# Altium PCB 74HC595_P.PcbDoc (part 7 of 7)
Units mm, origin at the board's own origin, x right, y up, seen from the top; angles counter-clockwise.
Board outline 89.11 x 89.03 mm, 2 copper layers (Top Layer, Bottom Layer); 552 components, 23 nets, 1488 pads, 408 vias.
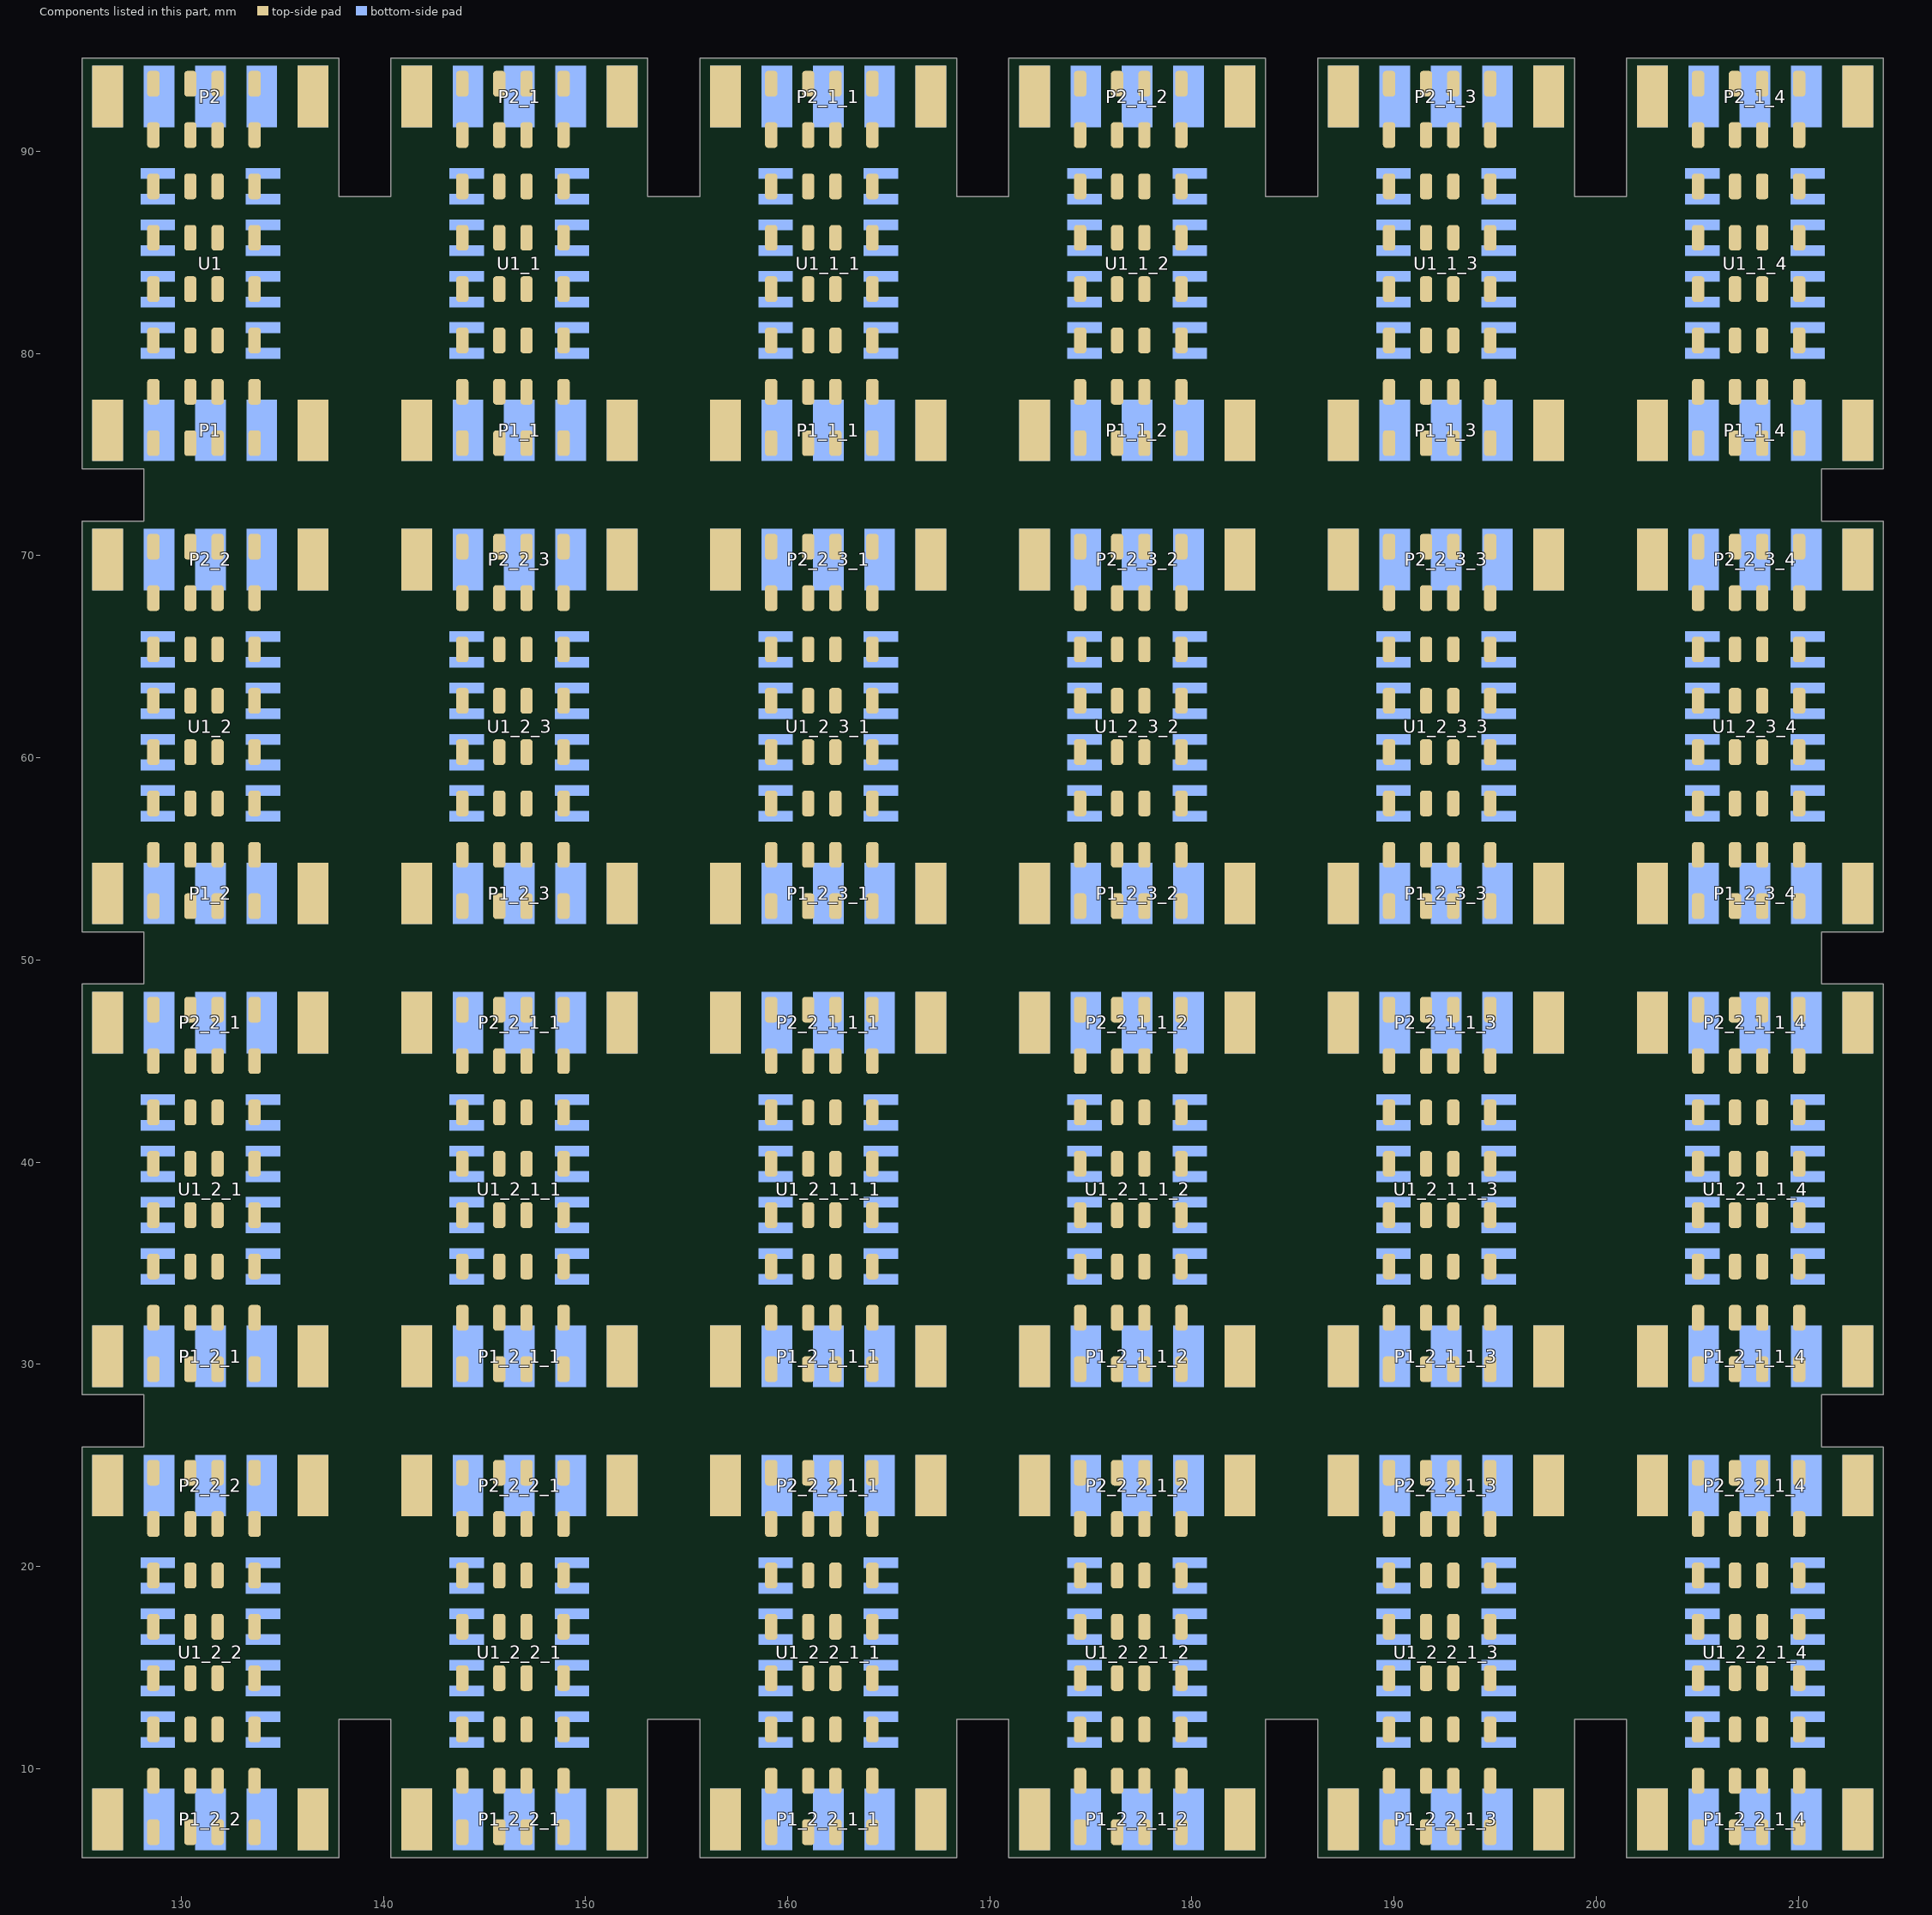
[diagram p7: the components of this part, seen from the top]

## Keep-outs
Keep-Out Layer:
  circle w0.1: c205.95,26.036 r0.275
  circle w0.1: c205.188,26.036 r0.275
  circle w0.1: c206.712,26.036 r0.275
  circle w0.1: c207.474,26.036 r0.275
  circle w0.1: c208.236,26.036 r0.275
  circle w0.1: c208.998,26.036 r0.275
  circle w0.1: c209.76,26.036 r0.275
  circle w0.1: c210.522,26.036 r0.275
  circle w0.1: c210.522,28.364 r0.275
  circle w0.1: c209.76,28.364 r0.275
  circle w0.1: c208.998,28.364 r0.275
  circle w0.1: c208.236,28.364 r0.275
  circle w0.1: c207.474,28.364 r0.275
  circle w0.1: c206.712,28.364 r0.275
  circle w0.1: c205.188,28.364 r0.275
  circle w0.1: c205.95,28.364 r0.275
  circle w0.1: c190.668,26.036 r0.275
  circle w0.1: c189.906,26.036 r0.275
  circle w0.1: c191.43,26.036 r0.275
  circle w0.1: c192.192,26.036 r0.275
  circle w0.1: c192.954,26.036 r0.275
  circle w0.1: c193.716,26.036 r0.275
  circle w0.1: c194.478,26.036 r0.275
  circle w0.1: c195.24,26.036 r0.275
  circle w0.1: c195.24,28.364 r0.275
  circle w0.1: c194.478,28.364 r0.275
  circle w0.1: c193.716,28.364 r0.275
  circle w0.1: c192.954,28.364 r0.275
  circle w0.1: c192.192,28.364 r0.275
  circle w0.1: c191.43,28.364 r0.275
  circle w0.1: c189.906,28.364 r0.275
  circle w0.1: c190.668,28.364 r0.275
  circle w0.1: c175.386,26.036 r0.275
  circle w0.1: c174.624,26.036 r0.275
  circle w0.1: c176.148,26.036 r0.275
  circle w0.1: c176.91,26.036 r0.275
  circle w0.1: c177.672,26.036 r0.275
  circle w0.1: c178.434,26.036 r0.275
  circle w0.1: c179.196,26.036 r0.275
  circle w0.1: c179.958,26.036 r0.275
  circle w0.1: c179.958,28.364 r0.275
  circle w0.1: c179.196,28.364 r0.275
  circle w0.1: c178.434,28.364 r0.275
  circle w0.1: c177.672,28.364 r0.275
  circle w0.1: c176.91,28.364 r0.275
  circle w0.1: c176.148,28.364 r0.275
  circle w0.1: c174.624,28.364 r0.275
  circle w0.1: c175.386,28.364 r0.275
  circle w0.1: c160.104,26.036 r0.275
  circle w0.1: c159.342,26.036 r0.275
  circle w0.1: c160.866,26.036 r0.275
  circle w0.1: c161.628,26.036 r0.275
  circle w0.1: c162.39,26.036 r0.275
  circle w0.1: c163.152,26.036 r0.275
  circle w0.1: c163.914,26.036 r0.275
  circle w0.1: c164.676,26.036 r0.275
  circle w0.1: c164.676,28.364 r0.275
  circle w0.1: c163.914,28.364 r0.275
  circle w0.1: c163.152,28.364 r0.275
  circle w0.1: c162.39,28.364 r0.275
  circle w0.1: c161.628,28.364 r0.275
  circle w0.1: c160.866,28.364 r0.275
  circle w0.1: c159.342,28.364 r0.275
  circle w0.1: c160.104,28.364 r0.275
  circle w0.1: c144.822,26.036 r0.275
  circle w0.1: c144.06,26.036 r0.275
  circle w0.1: c145.584,26.036 r0.275
  circle w0.1: c146.346,26.036 r0.275
  circle w0.1: c147.108,26.036 r0.275
  circle w0.1: c147.87,26.036 r0.275
  circle w0.1: c148.632,26.036 r0.275
  circle w0.1: c149.394,26.036 r0.275
  circle w0.1: c149.394,28.364 r0.275
  circle w0.1: c148.632,28.364 r0.275
  circle w0.1: c147.87,28.364 r0.275
  circle w0.1: c147.108,28.364 r0.275
  circle w0.1: c146.346,28.364 r0.275
  circle w0.1: c145.584,28.364 r0.275
  circle w0.1: c144.06,28.364 r0.275
  circle w0.1: c144.822,28.364 r0.275
  circle w0.1: c129.54,26.036 r0.275
  circle w0.1: c128.778,26.036 r0.275
  circle w0.1: c130.302,26.036 r0.275
  circle w0.1: c131.064,26.036 r0.275
  circle w0.1: c131.826,26.036 r0.275
  circle w0.1: c132.588,26.036 r0.275
  circle w0.1: c133.35,26.036 r0.275
  circle w0.1: c134.112,26.036 r0.275
  circle w0.1: c134.112,28.364 r0.275
  circle w0.1: c133.35,28.364 r0.275
  circle w0.1: c132.588,28.364 r0.275
  circle w0.1: c131.826,28.364 r0.275
  circle w0.1: c131.064,28.364 r0.275
  circle w0.1: c130.302,28.364 r0.275
  circle w0.1: c128.778,28.364 r0.275
  circle w0.1: c129.54,28.364 r0.275
  circle w0.1: c205.95,48.938 r0.275
  circle w0.1: c205.188,48.938 r0.275
  circle w0.1: c206.712,48.938 r0.275
  circle w0.1: c207.474,48.938 r0.275
  circle w0.1: c208.236,48.938 r0.275
  circle w0.1: c208.998,48.938 r0.275
  circle w0.1: c209.76,48.938 r0.275
  circle w0.1: c210.522,48.938 r0.275
  circle w0.1: c210.522,51.266 r0.275
  circle w0.1: c209.76,51.266 r0.275
  circle w0.1: c208.998,51.266 r0.275
  circle w0.1: c208.236,51.266 r0.275
  circle w0.1: c207.474,51.266 r0.275
  circle w0.1: c206.712,51.266 r0.275
  circle w0.1: c205.188,51.266 r0.275
  circle w0.1: c205.95,51.266 r0.275
  circle w0.1: c190.668,48.938 r0.275
  circle w0.1: c189.906,48.938 r0.275
  circle w0.1: c191.43,48.938 r0.275
  circle w0.1: c192.192,48.938 r0.275
  circle w0.1: c192.954,48.938 r0.275
  circle w0.1: c193.716,48.938 r0.275
  circle w0.1: c194.478,48.938 r0.275
  circle w0.1: c195.24,48.938 r0.275
  circle w0.1: c195.24,51.266 r0.275
  circle w0.1: c194.478,51.266 r0.275
  circle w0.1: c193.716,51.266 r0.275
  circle w0.1: c192.954,51.266 r0.275
  circle w0.1: c192.192,51.266 r0.275
  circle w0.1: c191.43,51.266 r0.275
  circle w0.1: c189.906,51.266 r0.275
  circle w0.1: c190.668,51.266 r0.275
  circle w0.1: c175.386,48.938 r0.275
  circle w0.1: c174.624,48.938 r0.275
  circle w0.1: c176.148,48.938 r0.275
  circle w0.1: c176.91,48.938 r0.275
  circle w0.1: c177.672,48.938 r0.275
  circle w0.1: c178.434,48.938 r0.275
  circle w0.1: c179.196,48.938 r0.275
  circle w0.1: c179.958,48.938 r0.275
  circle w0.1: c179.958,51.266 r0.275
  circle w0.1: c179.196,51.266 r0.275
  circle w0.1: c178.434,51.266 r0.275
  circle w0.1: c177.672,51.266 r0.275
  circle w0.1: c176.91,51.266 r0.275
  circle w0.1: c176.148,51.266 r0.275
  circle w0.1: c174.624,51.266 r0.275
  circle w0.1: c175.386,51.266 r0.275
  circle w0.1: c160.104,48.938 r0.275
  circle w0.1: c159.342,48.938 r0.275
  circle w0.1: c160.866,48.938 r0.275
  circle w0.1: c161.628,48.938 r0.275
  circle w0.1: c162.39,48.938 r0.275
  circle w0.1: c163.152,48.938 r0.275
  circle w0.1: c163.914,48.938 r0.275
  circle w0.1: c164.676,48.938 r0.275
  circle w0.1: c164.676,51.266 r0.275
  circle w0.1: c163.914,51.266 r0.275
  circle w0.1: c163.152,51.266 r0.275
  circle w0.1: c162.39,51.266 r0.275
  circle w0.1: c161.628,51.266 r0.275
  circle w0.1: c160.866,51.266 r0.275
  circle w0.1: c159.342,51.266 r0.275
  circle w0.1: c160.104,51.266 r0.275
  circle w0.1: c144.822,48.938 r0.275
  circle w0.1: c144.06,48.938 r0.275
  circle w0.1: c145.584,48.938 r0.275
  circle w0.1: c146.346,48.938 r0.275
  circle w0.1: c147.108,48.938 r0.275
  circle w0.1: c147.87,48.938 r0.275
  circle w0.1: c148.632,48.938 r0.275
  circle w0.1: c149.394,48.938 r0.275
  circle w0.1: c149.394,51.266 r0.275
  circle w0.1: c148.632,51.266 r0.275
  circle w0.1: c147.87,51.266 r0.275
  circle w0.1: c147.108,51.266 r0.275
  circle w0.1: c146.346,51.266 r0.275
  circle w0.1: c145.584,51.266 r0.275
  circle w0.1: c144.06,51.266 r0.275
  circle w0.1: c144.822,51.266 r0.275
  circle w0.1: c129.54,48.938 r0.275
  circle w0.1: c128.778,48.938 r0.275
  circle w0.1: c130.302,48.938 r0.275
  circle w0.1: c131.064,48.938 r0.275
  circle w0.1: c131.826,48.938 r0.275
  circle w0.1: c132.588,48.938 r0.275
  circle w0.1: c133.35,48.938 r0.275
  circle w0.1: c134.112,48.938 r0.275
  circle w0.1: c134.112,51.266 r0.275
  circle w0.1: c133.35,51.266 r0.275
  circle w0.1: c132.588,51.266 r0.275
  circle w0.1: c131.826,51.266 r0.275
  circle w0.1: c131.064,51.266 r0.275
  circle w0.1: c130.302,51.266 r0.275
  circle w0.1: c128.778,51.266 r0.275
  circle w0.1: c129.54,51.266 r0.275
  circle w0.1: c205.95,71.84 r0.275
  circle w0.1: c205.188,71.84 r0.275
  circle w0.1: c206.712,71.84 r0.275
  circle w0.1: c207.474,71.84 r0.275
  circle w0.1: c208.236,71.84 r0.275
  circle w0.1: c208.998,71.84 r0.275
  circle w0.1: c209.76,71.84 r0.275
  circle w0.1: c210.522,71.84 r0.275
  circle w0.1: c210.522,74.168 r0.275
  circle w0.1: c209.76,74.168 r0.275
  circle w0.1: c208.998,74.168 r0.275
  circle w0.1: c208.236,74.168 r0.275
  circle w0.1: c207.474,74.168 r0.275
  circle w0.1: c206.712,74.168 r0.275
  circle w0.1: c205.188,74.168 r0.275
  circle w0.1: c205.95,74.168 r0.275
  circle w0.1: c190.668,71.84 r0.275
  circle w0.1: c189.906,71.84 r0.275
  circle w0.1: c191.43,71.84 r0.275
  circle w0.1: c192.192,71.84 r0.275
  circle w0.1: c192.954,71.84 r0.275
  circle w0.1: c193.716,71.84 r0.275
  circle w0.1: c194.478,71.84 r0.275
  circle w0.1: c195.24,71.84 r0.275
  circle w0.1: c195.24,74.168 r0.275
  circle w0.1: c194.478,74.168 r0.275
  circle w0.1: c193.716,74.168 r0.275
  circle w0.1: c192.954,74.168 r0.275
  circle w0.1: c192.192,74.168 r0.275
  circle w0.1: c191.43,74.168 r0.275
  circle w0.1: c189.906,74.168 r0.275
  circle w0.1: c190.668,74.168 r0.275
  circle w0.1: c175.386,71.84 r0.275
  circle w0.1: c174.624,71.84 r0.275
  circle w0.1: c176.148,71.84 r0.275
  circle w0.1: c176.91,71.84 r0.275
  circle w0.1: c177.672,71.84 r0.275
  circle w0.1: c178.434,71.84 r0.275
  circle w0.1: c179.196,71.84 r0.275
  circle w0.1: c179.958,71.84 r0.275
  circle w0.1: c179.958,74.168 r0.275
  circle w0.1: c179.196,74.168 r0.275
  circle w0.1: c178.434,74.168 r0.275
  circle w0.1: c177.672,74.168 r0.275
  circle w0.1: c176.91,74.168 r0.275
  circle w0.1: c176.148,74.168 r0.275
  circle w0.1: c174.624,74.168 r0.275
  circle w0.1: c175.386,74.168 r0.275
  circle w0.1: c160.104,71.84 r0.275
  circle w0.1: c159.342,71.84 r0.275
  circle w0.1: c160.866,71.84 r0.275
  circle w0.1: c161.628,71.84 r0.275
  circle w0.1: c162.39,71.84 r0.275
  circle w0.1: c163.152,71.84 r0.275
  circle w0.1: c163.914,71.84 r0.275
  circle w0.1: c164.676,71.84 r0.275
  circle w0.1: c164.676,74.168 r0.275
  circle w0.1: c163.914,74.168 r0.275
  circle w0.1: c163.152,74.168 r0.275
  circle w0.1: c162.39,74.168 r0.275
  circle w0.1: c161.628,74.168 r0.275
  circle w0.1: c160.866,74.168 r0.275
  circle w0.1: c159.342,74.168 r0.275
  circle w0.1: c160.104,74.168 r0.275
  circle w0.1: c144.822,71.84 r0.275
  circle w0.1: c144.06,71.84 r0.275
  circle w0.1: c145.584,71.84 r0.275
  circle w0.1: c146.346,71.84 r0.275
  circle w0.1: c147.108,71.84 r0.275
  circle w0.1: c147.87,71.84 r0.275
  circle w0.1: c148.632,71.84 r0.275
  circle w0.1: c149.394,71.84 r0.275
  circle w0.1: c149.394,74.168 r0.275
  circle w0.1: c148.632,74.168 r0.275
  circle w0.1: c147.87,74.168 r0.275
  circle w0.1: c147.108,74.168 r0.275
  circle w0.1: c146.346,74.168 r0.275
  circle w0.1: c145.584,74.168 r0.275
  circle w0.1: c144.06,74.168 r0.275
  circle w0.1: c144.822,74.168 r0.275
  circle w0.1: c129.54,71.84 r0.275
  circle w0.1: c128.778,71.84 r0.275
  circle w0.1: c130.302,71.84 r0.275
  circle w0.1: c131.064,71.84 r0.275
  circle w0.1: c131.826,71.84 r0.275
  circle w0.1: c132.588,71.84 r0.275
  circle w0.1: c133.35,71.84 r0.275
  circle w0.1: c134.112,71.84 r0.275
  circle w0.1: c134.112,74.168 r0.275
  circle w0.1: c133.35,74.168 r0.275
  circle w0.1: c132.588,74.168 r0.275
  circle w0.1: c131.826,74.168 r0.275
  circle w0.1: c131.064,74.168 r0.275
  circle w0.1: c130.302,74.168 r0.275
  circle w0.1: c128.778,74.168 r0.275
  circle w0.1: c129.54,74.168 r0.275
  circle w0.1: c199.05,17.654 r0.275
  circle w0.1: c199.05,18.416 r0.275
  circle w0.1: c199.05,16.892 r0.275
  circle w0.1: c199.05,16.13 r0.275
  circle w0.1: c199.05,15.368 r0.275
  circle w0.1: c199.05,14.606 r0.275
  circle w0.1: c199.05,13.844 r0.275
  circle w0.1: c199.05,13.082 r0.275
  circle w0.1: c201.378,13.082 r0.275
  circle w0.1: c201.378,13.844 r0.275
  circle w0.1: c201.378,14.606 r0.275
  circle w0.1: c201.378,15.368 r0.275
  circle w0.1: c201.378,16.13 r0.275
  circle w0.1: c201.378,16.892 r0.275
  circle w0.1: c201.378,18.416 r0.275
  circle w0.1: c201.378,17.654 r0.275
  circle w0.1: c183.768,17.654 r0.275
  circle w0.1: c183.768,18.416 r0.275
  circle w0.1: c183.768,16.892 r0.275
  circle w0.1: c183.768,16.13 r0.275
  circle w0.1: c183.768,15.368 r0.275
  circle w0.1: c183.768,14.606 r0.275
  circle w0.1: c183.768,13.844 r0.275
  circle w0.1: c183.768,13.082 r0.275
  circle w0.1: c186.096,13.082 r0.275
  circle w0.1: c186.096,13.844 r0.275
  circle w0.1: c186.096,14.606 r0.275
  circle w0.1: c186.096,15.368 r0.275
  circle w0.1: c186.096,16.13 r0.275
  circle w0.1: c186.096,16.892 r0.275
  circle w0.1: c186.096,18.416 r0.275
  circle w0.1: c186.096,17.654 r0.275
  circle w0.1: c168.486,17.654 r0.275
  circle w0.1: c168.486,18.416 r0.275
  circle w0.1: c168.486,16.892 r0.275
  circle w0.1: c168.486,16.13 r0.275
  circle w0.1: c168.486,15.368 r0.275
  circle w0.1: c168.486,14.606 r0.275
  circle w0.1: c168.486,13.844 r0.275
  circle w0.1: c168.486,13.082 r0.275
  circle w0.1: c170.814,13.082 r0.275
  circle w0.1: c170.814,13.844 r0.275
  circle w0.1: c170.814,14.606 r0.275
  circle w0.1: c170.814,15.368 r0.275
  circle w0.1: c170.814,16.13 r0.275
  circle w0.1: c170.814,16.892 r0.275
  circle w0.1: c170.814,18.416 r0.275
  circle w0.1: c170.814,17.654 r0.275
  circle w0.1: c153.204,17.654 r0.275
  circle w0.1: c153.204,18.416 r0.275
  circle w0.1: c153.204,16.892 r0.275
  circle w0.1: c153.204,16.13 r0.275
  circle w0.1: c153.204,15.368 r0.275
  circle w0.1: c153.204,14.606 r0.275
  circle w0.1: c153.204,13.844 r0.275
  circle w0.1: c153.204,13.082 r0.275
  circle w0.1: c155.532,13.082 r0.275
  circle w0.1: c155.532,13.844 r0.275
  circle w0.1: c155.532,14.606 r0.275
  circle w0.1: c155.532,15.368 r0.275
  circle w0.1: c155.532,16.13 r0.275
  circle w0.1: c155.532,16.892 r0.275
  circle w0.1: c155.532,18.416 r0.275
  circle w0.1: c155.532,17.654 r0.275
  circle w0.1: c137.922,17.654 r0.275
  circle w0.1: c137.922,18.416 r0.275
  circle w0.1: c137.922,16.892 r0.275
  circle w0.1: c137.922,16.13 r0.275
  circle w0.1: c137.922,15.368 r0.275
  circle w0.1: c137.922,14.606 r0.275
  circle w0.1: c137.922,13.844 r0.275
  circle w0.1: c137.922,13.082 r0.275
  circle w0.1: c140.25,13.082 r0.275
  circle w0.1: c140.25,13.844 r0.275
  circle w0.1: c140.25,14.606 r0.275
  circle w0.1: c140.25,15.368 r0.275
  circle w0.1: c140.25,16.13 r0.275
  circle w0.1: c140.25,16.892 r0.275
  circle w0.1: c140.25,18.416 r0.275
  circle w0.1: c140.25,17.654 r0.275
  circle w0.1: c199.05,40.556 r0.275
  circle w0.1: c199.05,41.318 r0.275
  circle w0.1: c199.05,39.794 r0.275
  circle w0.1: c199.05,39.032 r0.275
  circle w0.1: c199.05,38.27 r0.275
  circle w0.1: c199.05,37.508 r0.275
  circle w0.1: c199.05,36.746 r0.275
  circle w0.1: c199.05,35.984 r0.275
  circle w0.1: c201.378,35.984 r0.275
  circle w0.1: c201.378,36.746 r0.275
  circle w0.1: c201.378,37.508 r0.275
  circle w0.1: c201.378,38.27 r0.275
  circle w0.1: c201.378,39.032 r0.275
  circle w0.1: c201.378,39.794 r0.275
  circle w0.1: c201.378,41.318 r0.275
  circle w0.1: c201.378,40.556 r0.275
  circle w0.1: c183.768,40.556 r0.275
  circle w0.1: c183.768,41.318 r0.275
  circle w0.1: c183.768,39.794 r0.275
  circle w0.1: c183.768,39.032 r0.275
  circle w0.1: c183.768,38.27 r0.275
  circle w0.1: c183.768,37.508 r0.275
  circle w0.1: c183.768,36.746 r0.275
  circle w0.1: c183.768,35.984 r0.275
  circle w0.1: c186.096,35.984 r0.275
  circle w0.1: c186.096,36.746 r0.275
  circle w0.1: c186.096,37.508 r0.275
  circle w0.1: c186.096,38.27 r0.275
  circle w0.1: c186.096,39.032 r0.275
  circle w0.1: c186.096,39.794 r0.275
  circle w0.1: c186.096,41.318 r0.275
  circle w0.1: c186.096,40.556 r0.275
  circle w0.1: c168.486,40.556 r0.275
  circle w0.1: c168.486,41.318 r0.275
  circle w0.1: c168.486,39.794 r0.275
  circle w0.1: c168.486,39.032 r0.275
  circle w0.1: c168.486,38.27 r0.275
  circle w0.1: c168.486,37.508 r0.275
  circle w0.1: c168.486,36.746 r0.275
  circle w0.1: c168.486,35.984 r0.275
  circle w0.1: c170.814,35.984 r0.275
  circle w0.1: c170.814,36.746 r0.275
  circle w0.1: c170.814,37.508 r0.275
  circle w0.1: c170.814,38.27 r0.275
  circle w0.1: c170.814,39.032 r0.275
  circle w0.1: c170.814,39.794 r0.275
  circle w0.1: c170.814,41.318 r0.275
  circle w0.1: c170.814,40.556 r0.275
  circle w0.1: c153.204,40.556 r0.275
  circle w0.1: c153.204,41.318 r0.275
  circle w0.1: c153.204,39.794 r0.275
  circle w0.1: c153.204,39.032 r0.275
  circle w0.1: c153.204,38.27 r0.275
  circle w0.1: c153.204,37.508 r0.275
  circle w0.1: c153.204,36.746 r0.275
  circle w0.1: c153.204,35.984 r0.275
  circle w0.1: c155.532,35.984 r0.275
  circle w0.1: c155.532,36.746 r0.275
  circle w0.1: c155.532,37.508 r0.275
  circle w0.1: c155.532,38.27 r0.275
  circle w0.1: c155.532,39.032 r0.275
  circle w0.1: c155.532,39.794 r0.275
  circle w0.1: c155.532,41.318 r0.275
  circle w0.1: c155.532,40.556 r0.275
  circle w0.1: c137.922,40.556 r0.275
  circle w0.1: c137.922,41.318 r0.275
  circle w0.1: c137.922,39.794 r0.275
  circle w0.1: c137.922,39.032 r0.275
  circle w0.1: c137.922,38.27 r0.275
  circle w0.1: c137.922,37.508 r0.275
  circle w0.1: c137.922,36.746 r0.275
  circle w0.1: c137.922,35.984 r0.275
  circle w0.1: c140.25,35.984 r0.275
  circle w0.1: c140.25,36.746 r0.275
  circle w0.1: c140.25,37.508 r0.275
  circle w0.1: c140.25,38.27 r0.275
  circle w0.1: c140.25,39.032 r0.275
  circle w0.1: c140.25,39.794 r0.275
  circle w0.1: c140.25,41.318 r0.275
  circle w0.1: c140.25,40.556 r0.275
  circle w0.1: c199.05,63.458 r0.275
  circle w0.1: c199.05,64.22 r0.275
  circle w0.1: c199.05,62.696 r0.275
  circle w0.1: c199.05,61.934 r0.275
  circle w0.1: c199.05,61.172 r0.275
  circle w0.1: c199.05,60.41 r0.275
  circle w0.1: c199.05,59.648 r0.275
  circle w0.1: c199.05,58.886 r0.275
  circle w0.1: c201.378,58.886 r0.275
  circle w0.1: c201.378,59.648 r0.275
  circle w0.1: c201.378,60.41 r0.275
  circle w0.1: c201.378,61.172 r0.275
  circle w0.1: c201.378,61.934 r0.275
  circle w0.1: c201.378,62.696 r0.275
  circle w0.1: c201.378,64.22 r0.275
  circle w0.1: c201.378,63.458 r0.275
  circle w0.1: c183.768,63.458 r0.275
  circle w0.1: c183.768,64.22 r0.275
  circle w0.1: c183.768,62.696 r0.275
  circle w0.1: c183.768,61.934 r0.275
  circle w0.1: c183.768,61.172 r0.275
  circle w0.1: c183.768,60.41 r0.275
  circle w0.1: c183.768,59.648 r0.275
  circle w0.1: c183.768,58.886 r0.275
  circle w0.1: c186.096,58.886 r0.275
  circle w0.1: c186.096,59.648 r0.275
  circle w0.1: c186.096,60.41 r0.275
  circle w0.1: c186.096,61.172 r0.275
  circle w0.1: c186.096,61.934 r0.275
  circle w0.1: c186.096,62.696 r0.275
  circle w0.1: c186.096,64.22 r0.275
  circle w0.1: c186.096,63.458 r0.275
  circle w0.1: c168.486,63.458 r0.275
  circle w0.1: c168.486,64.22 r0.275
  circle w0.1: c168.486,62.696 r0.275
  circle w0.1: c168.486,61.934 r0.275
  circle w0.1: c168.486,61.172 r0.275
  circle w0.1: c168.486,60.41 r0.275
  circle w0.1: c168.486,59.648 r0.275
  circle w0.1: c168.486,58.886 r0.275
  circle w0.1: c170.814,58.886 r0.275
  circle w0.1: c170.814,59.648 r0.275
  circle w0.1: c170.814,60.41 r0.275
  circle w0.1: c170.814,61.172 r0.275
  circle w0.1: c170.814,61.934 r0.275
  circle w0.1: c170.814,62.696 r0.275
  circle w0.1: c170.814,64.22 r0.275
  circle w0.1: c170.814,63.458 r0.275
  circle w0.1: c153.204,63.458 r0.275
  circle w0.1: c153.204,64.22 r0.275
  circle w0.1: c153.204,62.696 r0.275
  circle w0.1: c153.204,61.934 r0.275
  circle w0.1: c153.204,61.172 r0.275
  circle w0.1: c153.204,60.41 r0.275
  circle w0.1: c153.204,59.648 r0.275
  circle w0.1: c153.204,58.886 r0.275
  circle w0.1: c155.532,58.886 r0.275
  circle w0.1: c155.532,59.648 r0.275
  circle w0.1: c155.532,60.41 r0.275
  circle w0.1: c155.532,61.172 r0.275
  circle w0.1: c155.532,61.934 r0.275
  circle w0.1: c155.532,62.696 r0.275
  circle w0.1: c155.532,64.22 r0.275
  circle w0.1: c155.532,63.458 r0.275
  circle w0.1: c137.922,63.458 r0.275
  circle w0.1: c137.922,64.22 r0.275
  circle w0.1: c137.922,62.696 r0.275
  circle w0.1: c137.922,61.934 r0.275
  circle w0.1: c137.922,61.172 r0.275
  circle w0.1: c137.922,60.41 r0.275
  circle w0.1: c137.922,59.648 r0.275
  circle w0.1: c137.922,58.886 r0.275
  circle w0.1: c140.25,58.886 r0.275
  circle w0.1: c140.25,59.648 r0.275
  circle w0.1: c140.25,60.41 r0.275
  circle w0.1: c140.25,61.172 r0.275
  circle w0.1: c140.25,61.934 r0.275
  circle w0.1: c140.25,62.696 r0.275
  circle w0.1: c140.25,64.22 r0.275
  circle w0.1: c140.25,63.458 r0.275
  circle w0.1: c199.05,86.36 r0.275
  circle w0.1: c199.05,87.122 r0.275
  circle w0.1: c199.05,85.598 r0.275
  circle w0.1: c199.05,84.836 r0.275
  circle w0.1: c199.05,84.074 r0.275
  circle w0.1: c199.05,83.312 r0.275
  circle w0.1: c199.05,82.55 r0.275
  circle w0.1: c199.05,81.788 r0.275
  circle w0.1: c201.378,81.788 r0.275
  circle w0.1: c201.378,82.55 r0.275
  circle w0.1: c201.378,83.312 r0.275
  circle w0.1: c201.378,84.074 r0.275
  circle w0.1: c201.378,84.836 r0.275
  circle w0.1: c201.378,85.598 r0.275
  circle w0.1: c201.378,87.122 r0.275
  circle w0.1: c201.378,86.36 r0.275
  circle w0.1: c183.768,86.36 r0.275
  circle w0.1: c183.768,87.122 r0.275
  circle w0.1: c183.768,85.598 r0.275
  circle w0.1: c183.768,84.836 r0.275
  circle w0.1: c183.768,84.074 r0.275
  circle w0.1: c183.768,83.312 r0.275
  circle w0.1: c183.768,82.55 r0.275
  circle w0.1: c183.768,81.788 r0.275
  circle w0.1: c186.096,81.788 r0.275
  circle w0.1: c186.096,82.55 r0.275
  circle w0.1: c186.096,83.312 r0.275
  circle w0.1: c186.096,84.074 r0.275
  circle w0.1: c186.096,84.836 r0.275
  circle w0.1: c186.096,85.598 r0.275
  circle w0.1: c186.096,87.122 r0.275
  circle w0.1: c186.096,86.36 r0.275
  circle w0.1: c168.486,86.36 r0.275
  circle w0.1: c168.486,87.122 r0.275
  circle w0.1: c168.486,85.598 r0.275
  circle w0.1: c168.486,84.836 r0.275
  circle w0.1: c168.486,84.074 r0.275
  circle w0.1: c168.486,83.312 r0.275
  circle w0.1: c168.486,82.55 r0.275
  circle w0.1: c168.486,81.788 r0.275
  circle w0.1: c170.814,81.788 r0.275
  circle w0.1: c170.814,82.55 r0.275
  circle w0.1: c170.814,83.312 r0.275
  circle w0.1: c170.814,84.074 r0.275
  circle w0.1: c170.814,84.836 r0.275
  circle w0.1: c170.814,85.598 r0.275
  circle w0.1: c170.814,87.122 r0.275
  circle w0.1: c170.814,86.36 r0.275
  circle w0.1: c153.204,86.36 r0.275
  circle w0.1: c153.204,87.122 r0.275
  circle w0.1: c153.204,85.598 r0.275
  circle w0.1: c153.204,84.836 r0.275
  circle w0.1: c153.204,84.074 r0.275
  circle w0.1: c153.204,83.312 r0.275
  circle w0.1: c153.204,82.55 r0.275
  circle w0.1: c153.204,81.788 r0.275
  circle w0.1: c155.532,81.788 r0.275
  circle w0.1: c155.532,82.55 r0.275
  circle w0.1: c155.532,83.312 r0.275
  circle w0.1: c155.532,84.074 r0.275
  circle w0.1: c155.532,84.836 r0.275
  circle w0.1: c155.532,85.598 r0.275
  circle w0.1: c155.532,87.122 r0.275
  circle w0.1: c155.532,86.36 r0.275
  circle w0.1: c140.25,86.36 r0.275
  circle w0.1: c140.25,87.122 r0.275
  circle w0.1: c140.25,85.598 r0.275
  circle w0.1: c140.25,84.836 r0.275
  circle w0.1: c140.25,84.074 r0.275
  circle w0.1: c140.25,83.312 r0.275
  circle w0.1: c140.25,82.55 r0.275
  circle w0.1: c140.25,81.788 r0.275
  circle w0.1: c137.922,81.788 r0.275
  circle w0.1: c137.922,82.55 r0.275
  circle w0.1: c137.922,83.312 r0.275
  circle w0.1: c137.922,84.074 r0.275
  circle w0.1: c137.922,84.836 r0.275
  circle w0.1: c137.922,85.598 r0.275
  circle w0.1: c137.922,87.122 r0.275
  circle w0.1: c137.922,86.36 r0.275
  lines w0.254: 125.095,5.589 137.795,5.589 137.795,12.447 140.377,12.447 140.377,5.589 153.077,5.589 153.077,12.447 155.659,12.447 155.659,5.589 168.359,5.589 168.359,12.447 170.941,12.447 170.941,5.589 183.641,5.589 183.641,12.447 186.223,12.447 186.223,5.589 198.923,5.589 198.923,12.447 201.505,12.447 201.505,5.589 214.205,5.589 214.205,25.909 211.157,25.909 211.157,28.491 214.205,28.491 214.205,48.811 211.157,48.811 211.157,51.393 214.205,51.393 214.205,71.713 211.157,71.713 211.157,74.295 214.205,74.295 214.205,94.615 201.505,94.615 201.505,87.757 198.923,87.757 198.923,94.615 186.223,94.615 186.223,87.757 183.641,87.757 183.641,94.615 170.941,94.615 170.941,87.757 168.359,87.757 168.359,94.615 155.659,94.615 155.659,87.757 153.077,87.757 153.077,94.615 140.377,94.615 140.377,87.757 137.795,87.757 137.795,94.615 125.095,94.615 125.095,74.295 128.143,74.295 128.143,71.713 125.095,71.713 125.095,51.393 128.143,51.393 128.143,48.811 125.095,48.811 125.095,28.491 128.143,28.491 128.143,25.909 125.095,25.909 125.095,5.589 ; 134.747,25.909 134.747,28.491 137.795,28.491 137.795,35.349 140.377,35.349 140.377,28.491 143.425,28.491 143.425,25.909 140.377,25.909 140.377,19.051 137.795,19.051 137.795,25.909 134.747,25.909 ; 134.747,48.811 137.795,48.811 137.795,41.953 140.377,41.953 140.377,48.811 143.425,48.811 143.425,51.393 140.377,51.393 140.377,58.251 137.795,58.251 137.795,51.393 134.747,51.393 134.747,48.811 ; 134.747,71.713 137.795,71.713 137.795,64.855 140.377,64.855 140.377,71.713 143.425,71.713 143.425,74.295 140.377,74.295 140.377,81.153 137.795,81.153 137.795,74.295 134.747,74.295 134.747,71.713 ; 150.029,25.909 150.029,28.491 153.077,28.491 153.077,35.349 155.659,35.349 155.659,28.491 158.707,28.491 158.707,25.909 155.659,25.909 155.659,19.051 153.077,19.051 153.077,25.909 150.029,25.909 ; 150.029,48.811 150.029,51.393 153.077,51.393 153.077,58.251 155.659,58.251 155.659,51.393 158.707,51.393 158.707,48.811 155.659,48.811 155.659,41.953 153.077,41.953 153.077,48.811 150.029,48.811 ; 150.029,71.713 153.077,71.713 153.077,64.855 155.659,64.855 155.659,71.713 158.707,71.713 158.707,74.295 155.659,74.295 155.659,81.153 153.077,81.153 153.077,74.295 150.029,74.295 150.029,71.713 ; 165.311,25.909 165.311,28.491 168.359,28.491 168.359,35.349 170.941,35.349 170.941,28.491 173.989,28.491 173.989,25.909 170.941,25.909 170.941,19.051 168.359,19.051 168.359,25.909 165.311,25.909 ; 165.311,48.811 165.311,51.393 168.359,51.393 168.359,58.251 170.941,58.251 170.941,51.393 173.989,51.393 173.989,48.811 170.941,48.811 170.941,41.953 168.359,41.953 168.359,48.811 165.311,48.811 ; 165.311,71.713 165.311,74.295 168.359,74.295 168.359,81.153 170.941,81.153 170.941,74.295 173.989,74.295 173.989,71.713 170.941,71.713 170.941,64.855 168.359,64.855 168.359,71.713 165.311,71.713 ; 180.593,25.909 180.593,28.491 183.641,28.491 183.641,35.349 186.223,35.349 186.223,28.491 189.271,28.491 189.271,25.909 186.223,25.909 186.223,19.051 183.641,19.051 183.641,25.909 180.593,25.909 ; 180.593,48.811 180.593,51.393 183.641,51.393 183.641,58.251 186.223,58.251 186.223,51.393 189.271,51.393 189.271,48.811 186.223,48.811 186.223,41.953 183.641,41.953 183.641,48.811 180.593,48.811 ; 180.593,71.713 180.593,74.295 183.641,74.295 183.641,81.153 186.223,81.153 186.223,74.295 189.271,74.295 189.271,71.713 186.223,71.713 186.223,64.855 183.641,64.855 183.641,71.713 180.593,71.713 ; 195.875,25.909 195.875,28.491 198.923,28.491 198.923,35.349 201.505,35.349 201.505,28.491 204.553,28.491 204.553,25.909 201.505,25.909 201.505,19.051 198.923,19.051 198.923,25.909 195.875,25.909 ; 195.875,48.811 195.875,51.393 198.923,51.393 198.923,58.251 201.505,58.251 201.505,51.393 204.553,51.393 204.553,48.811 201.505,48.811 201.505,41.953 198.923,41.953 198.923,48.811 195.875,48.811 ; 195.875,71.713 195.875,74.295 198.923,74.295 198.923,81.153 201.505,81.153 201.505,74.295 204.553,74.295 204.553,71.713 201.505,71.713 201.505,64.855 198.923,64.855 198.923,71.713 195.875,71.713

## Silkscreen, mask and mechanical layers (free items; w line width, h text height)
Top Overlay:
  text "GND" at 136.525,90.17 h1.52 r270
  text "GND" at 151.807,90.17 h1.52 r270
  text "GND" at 167.089,90.17 h1.52 r270
  text "GND" at 182.371,90.17 h1.52 r270
  text "GND" at 197.653,90.17 h1.52 r270
  text "GND" at 212.935,90.17 h1.52 r270
  text "VCC" at 125.476,89.535 h1.52 r270
  text "VCC" at 140.758,89.535 h1.52 r270
  text "VCC" at 156.04,89.535 h1.52 r270
  text "VCC" at 171.322,89.535 h1.52 r270
  text "VCC" at 186.604,89.535 h1.52 r270
  text "VCC" at 201.886,89.535 h1.52 r270
  text "GND" at 136.525,83.82 h1.52 r270
  text "GND" at 151.807,83.82 h1.52 r270
  text "GND" at 167.089,83.82 h1.52 r270
  text "GND" at 182.371,83.82 h1.52 r270
  text "GND" at 197.653,83.82 h1.52 r270
  text "GND" at 212.935,83.82 h1.52 r270
  text "VCC" at 125.476,82.55 h1.52 r270
  text "VCC" at 140.758,82.55 h1.52 r270
  text "VCC" at 156.04,82.55 h1.52 r270
  text "VCC" at 171.322,82.55 h1.52 r270
  text "VCC" at 186.604,82.55 h1.52 r270
  text "VCC" at 201.886,82.55 h1.52 r270
  text "GND" at 136.525,67.268 h1.52 r270
  text "GND" at 151.807,67.268 h1.52 r270
  text "GND" at 167.089,67.268 h1.52 r270
  text "GND" at 182.371,67.268 h1.52 r270
  text "GND" at 197.653,67.268 h1.52 r270
  text "GND" at 212.935,67.268 h1.52 r270
  text "VCC" at 125.476,66.633 h1.52 r270
  text "VCC" at 140.758,66.633 h1.52 r270
  text "VCC" at 156.04,66.633 h1.52 r270
  text "VCC" at 171.322,66.633 h1.52 r270
  text "VCC" at 186.604,66.633 h1.52 r270
  text "VCC" at 201.886,66.633 h1.52 r270
  text "GND" at 136.525,60.918 h1.52 r270
  text "GND" at 151.807,60.918 h1.52 r270
  text "GND" at 167.089,60.918 h1.52 r270
  text "GND" at 182.371,60.918 h1.52 r270
  text "GND" at 197.653,60.918 h1.52 r270
  text "GND" at 212.935,60.918 h1.52 r270
  text "VCC" at 125.476,59.648 h1.52 r270
  text "VCC" at 140.758,59.648 h1.52 r270
  text "VCC" at 156.04,59.648 h1.52 r270
  text "VCC" at 171.322,59.648 h1.52 r270
  text "VCC" at 186.604,59.648 h1.52 r270
  text "VCC" at 201.886,59.648 h1.52 r270
  text "GND" at 136.525,44.366 h1.52 r270
  text "GND" at 151.807,44.366 h1.52 r270
  text "GND" at 167.089,44.366 h1.52 r270
  text "GND" at 182.371,44.366 h1.52 r270
  text "GND" at 197.653,44.366 h1.52 r270
  text "GND" at 212.935,44.366 h1.52 r270
  text "VCC" at 125.476,43.731 h1.52 r270
  text "VCC" at 140.758,43.731 h1.52 r270
  text "VCC" at 156.04,43.731 h1.52 r270
  text "VCC" at 171.322,43.731 h1.52 r270
  text "VCC" at 186.604,43.731 h1.52 r270
  text "VCC" at 201.886,43.731 h1.52 r270
  text "GND" at 136.525,38.016 h1.52 r270
  text "GND" at 151.807,38.016 h1.52 r270
  text "GND" at 167.089,38.016 h1.52 r270
  text "GND" at 182.371,38.016 h1.52 r270
  text "GND" at 197.653,38.016 h1.52 r270
  text "GND" at 212.935,38.016 h1.52 r270
  text "VCC" at 125.476,36.746 h1.52 r270
  text "VCC" at 140.758,36.746 h1.52 r270
  text "VCC" at 156.04,36.746 h1.52 r270
  text "VCC" at 171.322,36.746 h1.52 r270
  text "VCC" at 186.604,36.746 h1.52 r270
  text "VCC" at 201.886,36.746 h1.52 r270
  text "GND" at 136.525,21.464 h1.52 r270
  text "GND" at 151.807,21.464 h1.52 r270
  text "GND" at 167.089,21.464 h1.52 r270
  text "GND" at 182.371,21.464 h1.52 r270
  text "GND" at 197.653,21.464 h1.52 r270
  text "GND" at 212.935,21.464 h1.52 r270
  text "VCC" at 125.476,20.829 h1.52 r270
  text "VCC" at 140.758,20.829 h1.52 r270
  text "VCC" at 156.04,20.829 h1.52 r270
  text "VCC" at 171.322,20.829 h1.52 r270
  text "VCC" at 186.604,20.829 h1.52 r270
  text "VCC" at 201.886,20.829 h1.52 r270
  text "GND" at 136.525,15.114 h1.52 r270
  text "GND" at 151.807,15.114 h1.52 r270
  text "GND" at 167.089,15.114 h1.52 r270
  text "GND" at 182.371,15.114 h1.52 r270
  text "GND" at 197.653,15.114 h1.52 r270
  text "GND" at 212.935,15.114 h1.52 r270
  text "VCC" at 125.476,13.844 h1.52 r270
  text "VCC" at 140.758,13.844 h1.52 r270
  text "VCC" at 156.04,13.844 h1.52 r270
  text "VCC" at 171.322,13.844 h1.52 r270
  text "VCC" at 186.604,13.844 h1.52 r270
  text "VCC" at 201.886,13.844 h1.52 r270
Bottom Overlay:
  text "data" at 127.381,89.789 h1.14
  text "bout" at 129.921,89.789 h1.14
  text "bclk" at 132.588,89.789 h1.14
  text "enab" at 137.541,89.789 h1.14
  text "data" at 142.663,89.789 h1.14
  text "bout" at 145.203,89.789 h1.14
  text "bclk" at 147.87,89.789 h1.14
  text "enab" at 152.823,89.789 h1.14
  text "data" at 157.945,89.789 h1.14
  text "bout" at 160.485,89.789 h1.14
  text "bclk" at 163.152,89.789 h1.14
  text "enab" at 168.105,89.789 h1.14
  text "data" at 173.227,89.789 h1.14
  text "bout" at 175.767,89.789 h1.14
  text "bclk" at 178.434,89.789 h1.14
  text "enab" at 183.387,89.789 h1.14
  text "data" at 188.509,89.789 h1.14
  text "bout" at 191.049,89.789 h1.14
  text "bclk" at 193.716,89.789 h1.14
  text "enab" at 198.669,89.789 h1.14
  text "data" at 203.791,89.789 h1.14
  text "bout" at 206.331,89.789 h1.14
  text "bclk" at 208.998,89.789 h1.14
  text "enab" at 213.951,89.789 h1.14
  text "data" at 127.381,78.359 h1.14
  text "bout" at 129.921,78.359 h1.14
  text "bclk" at 132.588,78.359 h1.14
  text "mclk" at 135.001,78.359 h1.14
  text "enab" at 137.541,78.359 h1.14
  text "data" at 142.663,78.359 h1.14
  text "bout" at 145.203,78.359 h1.14
  text "bclk" at 147.87,78.359 h1.14
  text "mclk" at 150.283,78.359 h1.14
  text "enab" at 152.823,78.359 h1.14
  text "data" at 157.945,78.359 h1.14
  text "bout" at 160.485,78.359 h1.14
  text "bclk" at 163.152,78.359 h1.14
  text "mclk" at 165.565,78.359 h1.14
  text "enab" at 168.105,78.359 h1.14
  text "data" at 173.227,78.359 h1.14
  text "bout" at 175.767,78.359 h1.14
  text "bclk" at 178.434,78.359 h1.14
  text "mclk" at 180.847,78.359 h1.14
  text "enab" at 183.387,78.359 h1.14
  text "data" at 188.509,78.359 h1.14
  text "bout" at 191.049,78.359 h1.14
  text "bclk" at 193.716,78.359 h1.14
  text "mclk" at 196.129,78.359 h1.14
  text "enab" at 198.669,78.359 h1.14
  text "data" at 203.791,78.359 h1.14
  text "bout" at 206.331,78.359 h1.14
  text "bclk" at 208.998,78.359 h1.14
  text "mclk" at 211.411,78.359 h1.14
  text "enab" at 213.951,78.359 h1.14
  text "data" at 127.381,66.887 h1.14
  text "bout" at 129.921,66.887 h1.14
  text "bclk" at 132.588,66.887 h1.14
  text "enab" at 137.541,66.887 h1.14
  text "data" at 142.663,66.887 h1.14
  text "bout" at 145.203,66.887 h1.14
  text "bclk" at 147.87,66.887 h1.14
  text "enab" at 152.823,66.887 h1.14
  text "data" at 157.945,66.887 h1.14
  text "bout" at 160.485,66.887 h1.14
  text "bclk" at 163.152,66.887 h1.14
  text "enab" at 168.105,66.887 h1.14
  text "data" at 173.227,66.887 h1.14
  text "bout" at 175.767,66.887 h1.14
  text "bclk" at 178.434,66.887 h1.14
  text "enab" at 183.387,66.887 h1.14
  text "data" at 188.509,66.887 h1.14
  text "bout" at 191.049,66.887 h1.14
  text "bclk" at 193.716,66.887 h1.14
  text "enab" at 198.669,66.887 h1.14
  text "data" at 203.791,66.887 h1.14
  text "bout" at 206.331,66.887 h1.14
  text "bclk" at 208.998,66.887 h1.14
  text "enab" at 213.951,66.887 h1.14
  text "data" at 127.381,55.457 h1.14
  text "bout" at 129.921,55.457 h1.14
  text "bclk" at 132.588,55.457 h1.14
  text "mclk" at 135.001,55.457 h1.14
  text "enab" at 137.541,55.457 h1.14
  text "data" at 142.663,55.457 h1.14
  text "bout" at 145.203,55.457 h1.14
  text "bclk" at 147.87,55.457 h1.14
  text "mclk" at 150.283,55.457 h1.14
  text "enab" at 152.823,55.457 h1.14
  text "data" at 157.945,55.457 h1.14
  text "bout" at 160.485,55.457 h1.14
  text "bclk" at 163.152,55.457 h1.14
  text "mclk" at 165.565,55.457 h1.14
  text "enab" at 168.105,55.457 h1.14
  text "data" at 173.227,55.457 h1.14
  text "bout" at 175.767,55.457 h1.14
  text "bclk" at 178.434,55.457 h1.14
  text "mclk" at 180.847,55.457 h1.14
  text "enab" at 183.387,55.457 h1.14
  text "data" at 188.509,55.457 h1.14
  text "bout" at 191.049,55.457 h1.14
  text "bclk" at 193.716,55.457 h1.14
  text "mclk" at 196.129,55.457 h1.14
  text "enab" at 198.669,55.457 h1.14
  text "data" at 203.791,55.457 h1.14
  text "bout" at 206.331,55.457 h1.14
  text "bclk" at 208.998,55.457 h1.14
  text "mclk" at 211.411,55.457 h1.14
  text "enab" at 213.951,55.457 h1.14
  text "data" at 127.381,43.985 h1.14
  text "bout" at 129.921,43.985 h1.14
  text "bclk" at 132.588,43.985 h1.14
  text "enab" at 137.541,43.985 h1.14
  text "data" at 142.663,43.985 h1.14
  text "bout" at 145.203,43.985 h1.14
  text "bclk" at 147.87,43.985 h1.14
  text "enab" at 152.823,43.985 h1.14
  text "data" at 157.945,43.985 h1.14
  text "bout" at 160.485,43.985 h1.14
  text "bclk" at 163.152,43.985 h1.14
  text "enab" at 168.105,43.985 h1.14
  text "data" at 173.227,43.985 h1.14
  text "bout" at 175.767,43.985 h1.14
  text "bclk" at 178.434,43.985 h1.14
  text "enab" at 183.387,43.985 h1.14
  text "data" at 188.509,43.985 h1.14
  text "bout" at 191.049,43.985 h1.14
  text "bclk" at 193.716,43.985 h1.14
  text "enab" at 198.669,43.985 h1.14
  text "data" at 203.791,43.985 h1.14
  text "bout" at 206.331,43.985 h1.14
  text "bclk" at 208.998,43.985 h1.14
  text "enab" at 213.951,43.985 h1.14
  text "data" at 127.381,32.555 h1.14
  text "bout" at 129.921,32.555 h1.14
  text "bclk" at 132.588,32.555 h1.14
  text "mclk" at 135.001,32.555 h1.14
  text "enab" at 137.541,32.555 h1.14
  text "data" at 142.663,32.555 h1.14
  text "bout" at 145.203,32.555 h1.14
  text "bclk" at 147.87,32.555 h1.14
  text "mclk" at 150.283,32.555 h1.14
  text "enab" at 152.823,32.555 h1.14
  text "data" at 157.945,32.555 h1.14
  text "bout" at 160.485,32.555 h1.14
  text "bclk" at 163.152,32.555 h1.14
  text "mclk" at 165.565,32.555 h1.14
  text "enab" at 168.105,32.555 h1.14
  text "data" at 173.227,32.555 h1.14
  text "bout" at 175.767,32.555 h1.14
  text "bclk" at 178.434,32.555 h1.14
  text "mclk" at 180.847,32.555 h1.14
  text "enab" at 183.387,32.555 h1.14
  text "data" at 188.509,32.555 h1.14
  text "bout" at 191.049,32.555 h1.14
  text "bclk" at 193.716,32.555 h1.14
  text "mclk" at 196.129,32.555 h1.14
  text "enab" at 198.669,32.555 h1.14
  text "data" at 203.791,32.555 h1.14
  text "bout" at 206.331,32.555 h1.14
  text "bclk" at 208.998,32.555 h1.14
  text "mclk" at 211.411,32.555 h1.14
  text "enab" at 213.951,32.555 h1.14
  text "data" at 127.381,21.083 h1.14
  text "bout" at 129.921,21.083 h1.14
  text "bclk" at 132.588,21.083 h1.14
  text "enab" at 137.541,21.083 h1.14
  text "data" at 142.663,21.083 h1.14
  text "bout" at 145.203,21.083 h1.14
  text "bclk" at 147.87,21.083 h1.14
  text "enab" at 152.823,21.083 h1.14
  text "data" at 157.945,21.083 h1.14
  text "bout" at 160.485,21.083 h1.14
  text "bclk" at 163.152,21.083 h1.14
  text "enab" at 168.105,21.083 h1.14
  text "data" at 173.227,21.083 h1.14
  text "bout" at 175.767,21.083 h1.14
  text "bclk" at 178.434,21.083 h1.14
  text "enab" at 183.387,21.083 h1.14
  text "data" at 188.509,21.083 h1.14
  text "bout" at 191.049,21.083 h1.14
  text "bclk" at 193.716,21.083 h1.14
  text "enab" at 198.669,21.083 h1.14
  text "data" at 203.791,21.083 h1.14
  text "bout" at 206.331,21.083 h1.14
  text "bclk" at 208.998,21.083 h1.14
  text "enab" at 213.951,21.083 h1.14
  text "data" at 127.381,9.653 h1.14
  text "bout" at 129.921,9.653 h1.14
  text "bclk" at 132.588,9.653 h1.14
  text "mclk" at 135.001,9.653 h1.14
  text "enab" at 137.541,9.653 h1.14
  text "data" at 142.663,9.653 h1.14
  text "bout" at 145.203,9.653 h1.14
  text "bclk" at 147.87,9.653 h1.14
  text "mclk" at 150.283,9.653 h1.14
  text "enab" at 152.823,9.653 h1.14
  text "data" at 157.945,9.653 h1.14
  text "bout" at 160.485,9.653 h1.14
  text "bclk" at 163.152,9.653 h1.14
  text "mclk" at 165.565,9.653 h1.14
  text "enab" at 168.105,9.653 h1.14
  text "data" at 173.227,9.653 h1.14
  text "bout" at 175.767,9.653 h1.14
  text "bclk" at 178.434,9.653 h1.14
  text "mclk" at 180.847,9.653 h1.14
  text "enab" at 183.387,9.653 h1.14
  text "data" at 188.509,9.653 h1.14
  text "bout" at 191.049,9.653 h1.14
  text "bclk" at 193.716,9.653 h1.14
  text "mclk" at 196.129,9.653 h1.14
  text "enab" at 198.669,9.653 h1.14
  text "data" at 203.791,9.653 h1.14
  text "bout" at 206.331,9.653 h1.14
  text "bclk" at 208.998,9.653 h1.14
  text "mclk" at 211.411,9.653 h1.14
  text "enab" at 213.951,9.653 h1.14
